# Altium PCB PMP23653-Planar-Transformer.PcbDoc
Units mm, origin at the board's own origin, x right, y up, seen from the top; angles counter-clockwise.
Board outline 30.4 x 20.9 mm, 6 copper layers (Top Layer, Int1, Int2, Int3, Int4, Bottom Layer), stack 2.081 mm thick; 6 components, 2 nets, 18 pads, 29 vias.
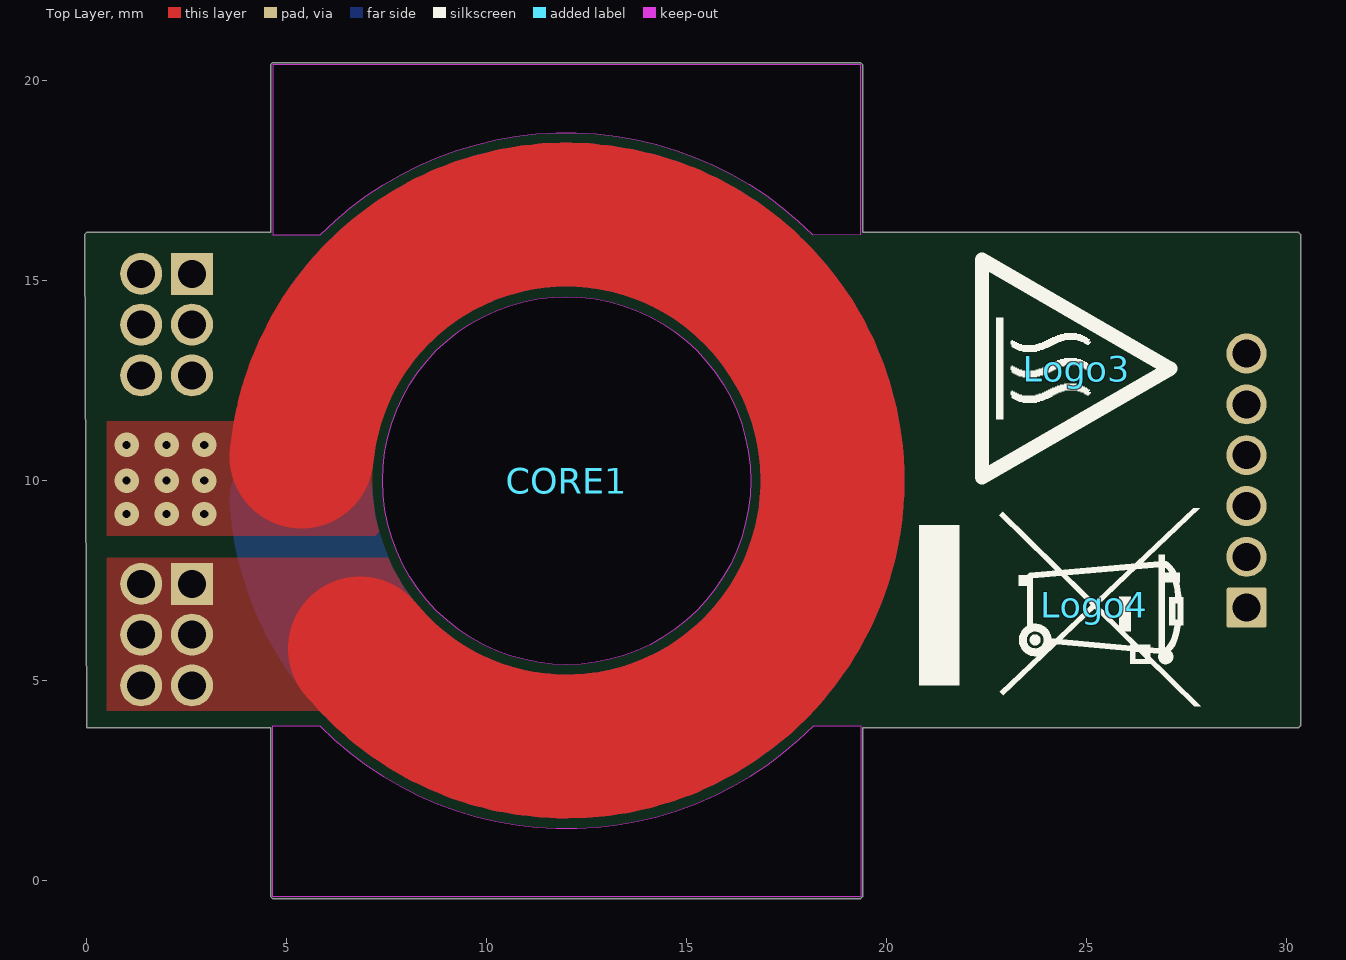
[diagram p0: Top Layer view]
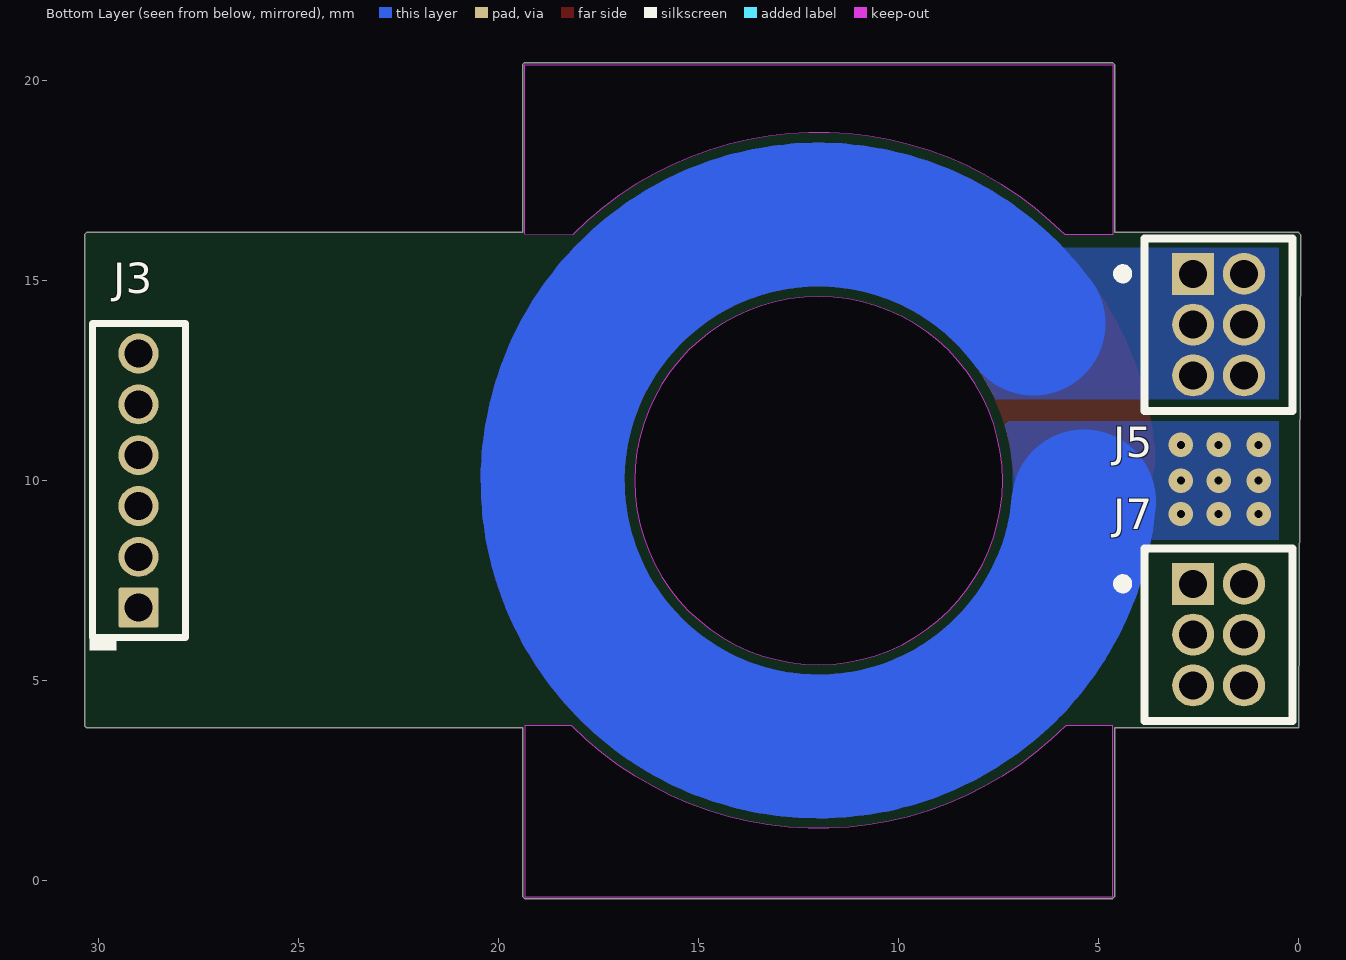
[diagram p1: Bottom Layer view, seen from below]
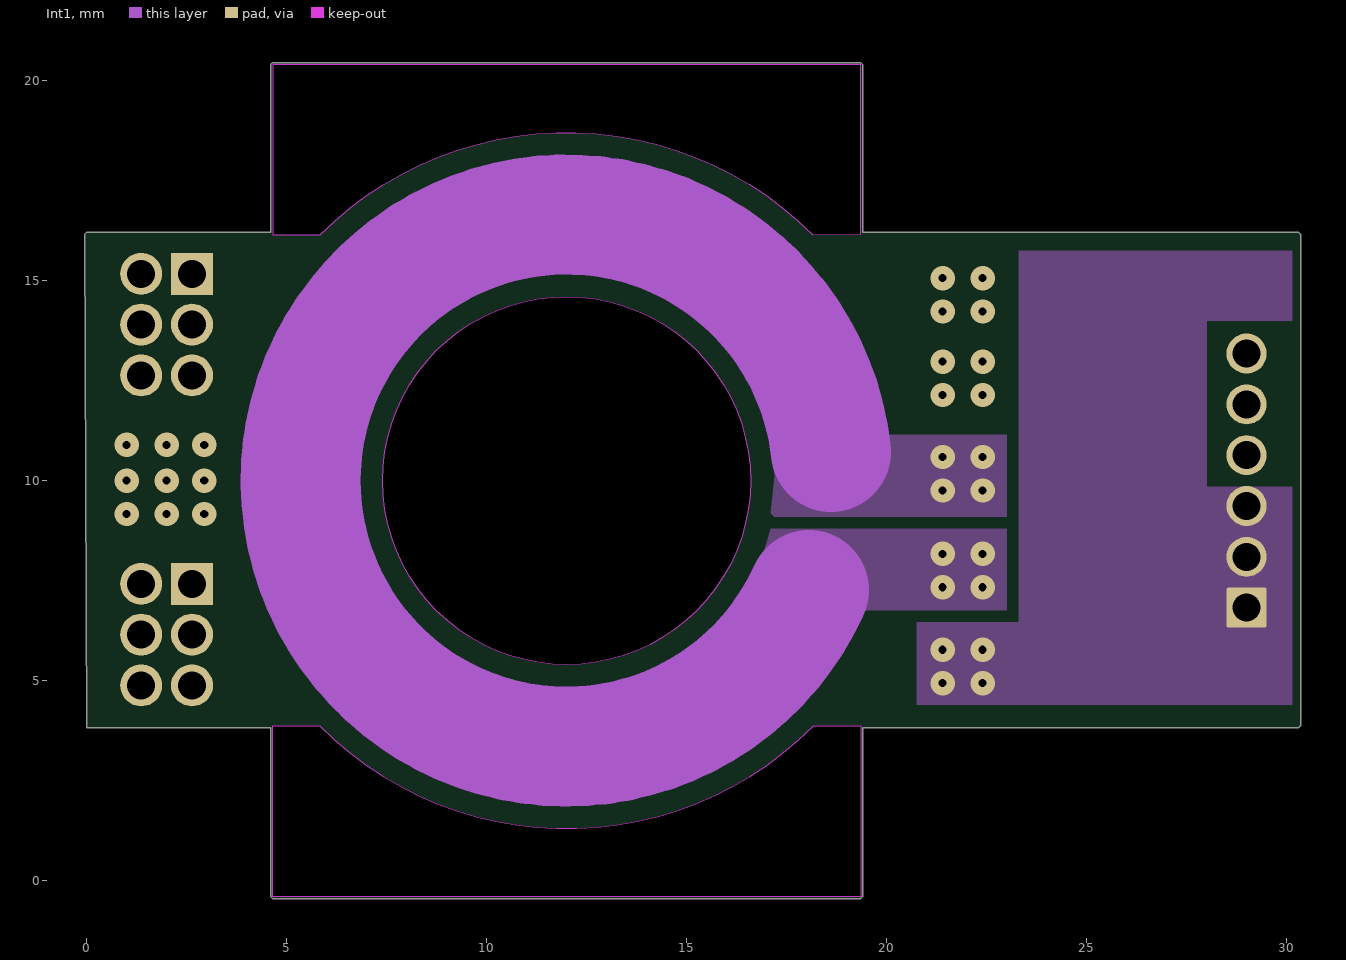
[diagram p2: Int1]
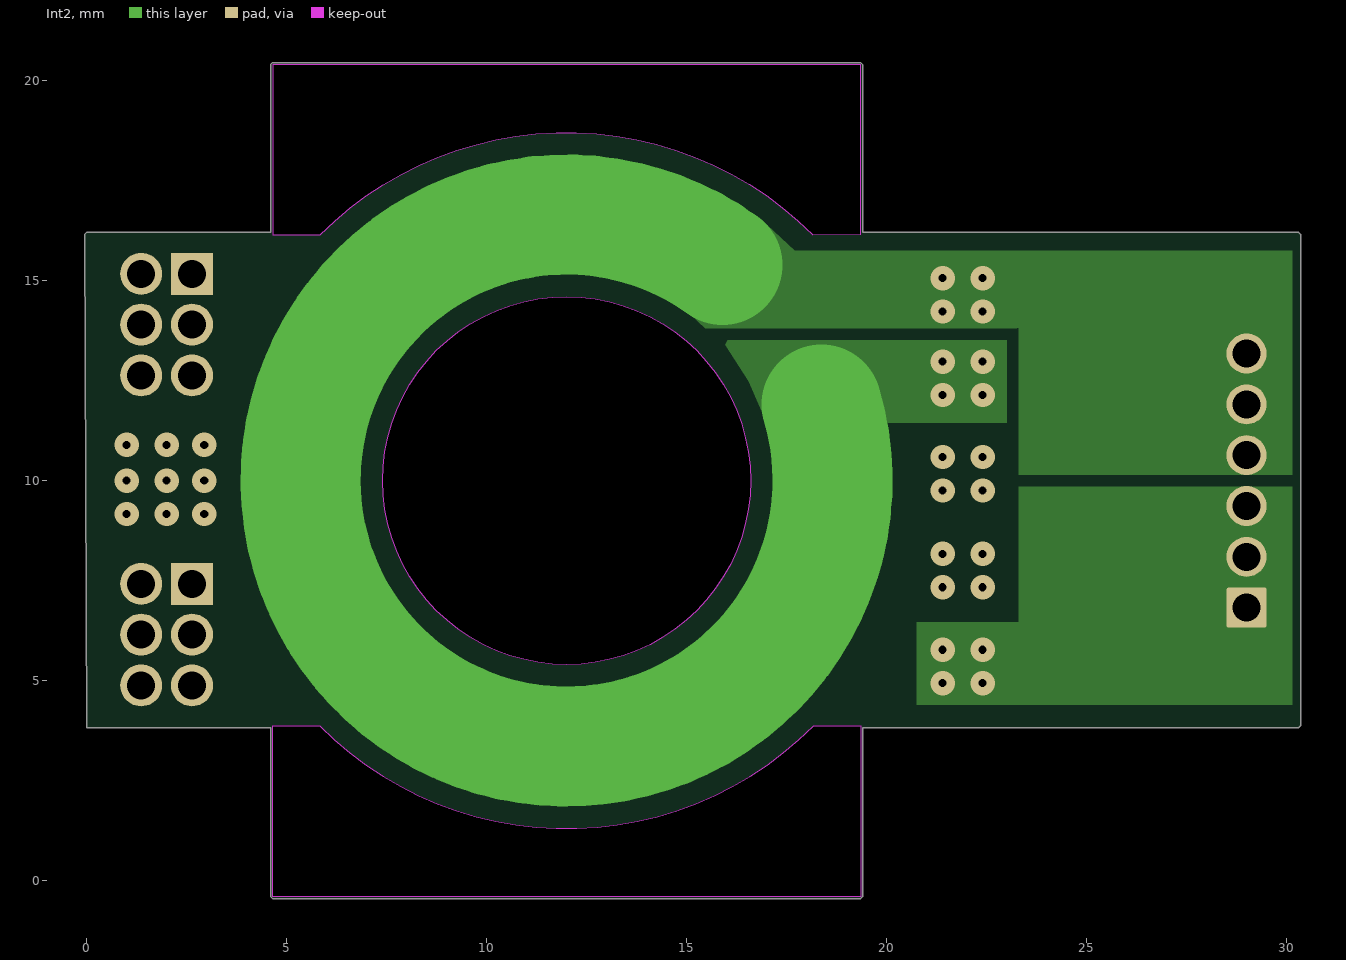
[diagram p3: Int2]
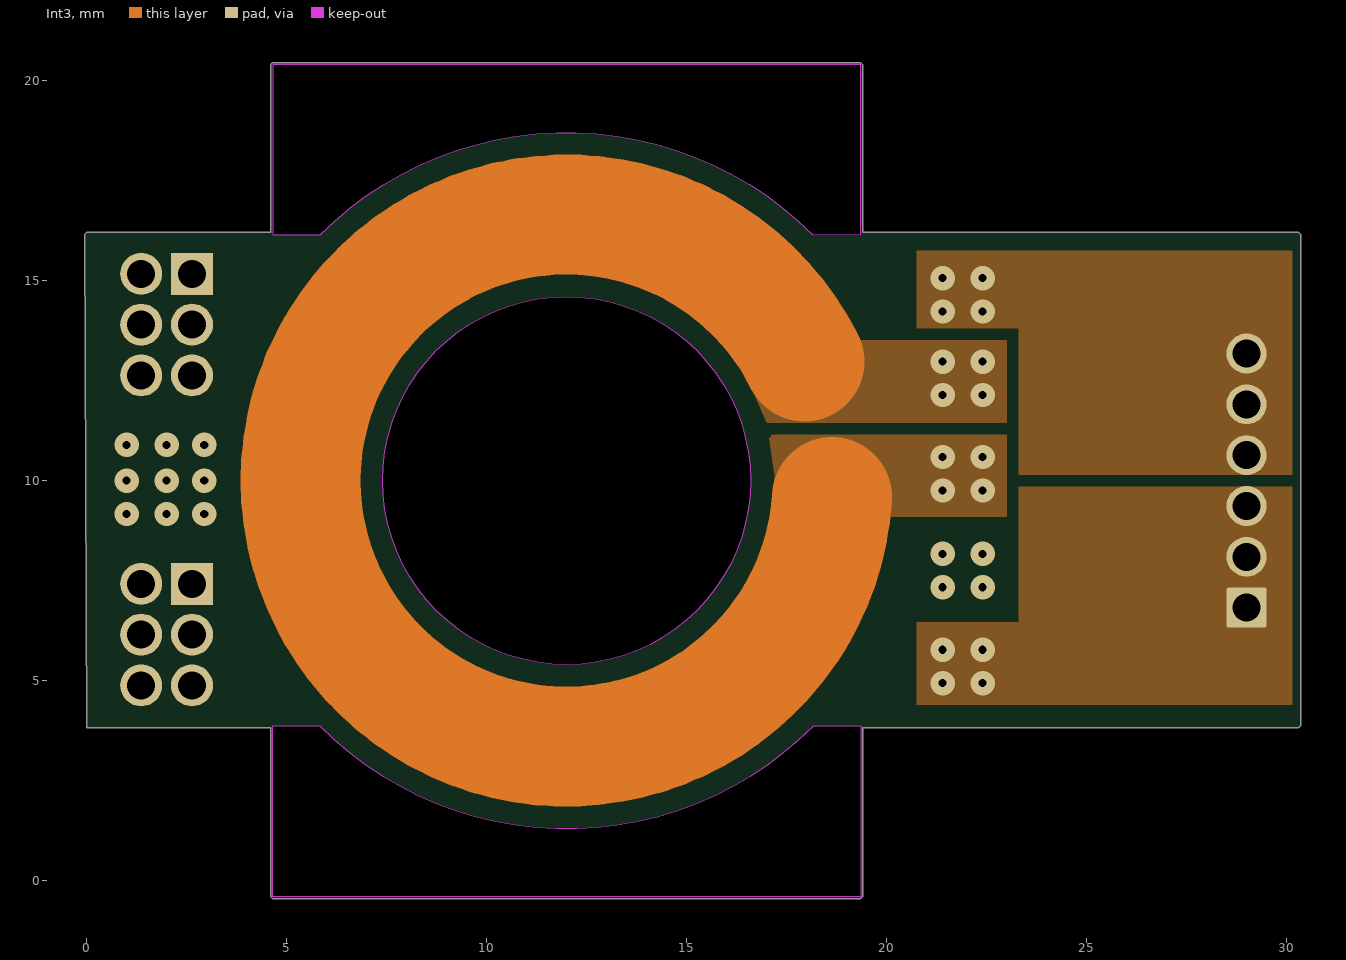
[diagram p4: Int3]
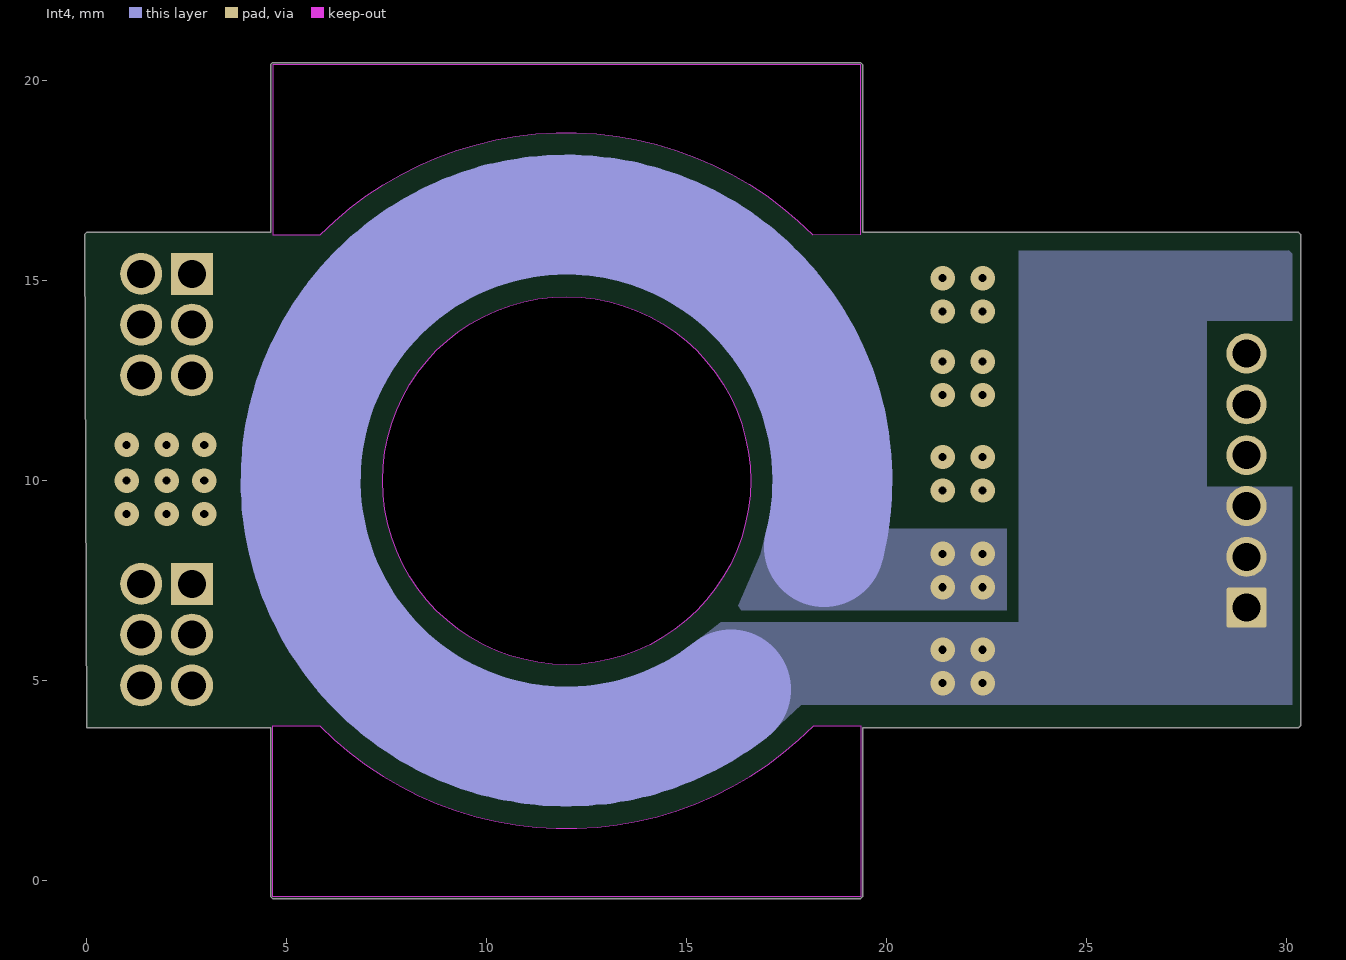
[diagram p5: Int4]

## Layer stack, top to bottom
Top Solder: solder mask 0.0254, SM-001, Dk 4
Top Layer: signal copper 0.07
Dielectric 1: core 0.508, Core-036, Dk 4.6
Dielectric 2: prepreg 0.0584, PP-003, Dk 3.9
Int1: signal copper 0.07
Dielectric 3: core 0.1778, Core-022, Dk 4.3
Int2: signal copper 0.07
Dielectric 4: prepreg 0.0864, PP-010, Dk 4
Dielectric 5: prepreg 0.0864, PP-010, Dk 4
Int3: signal copper 0.07
Dielectric 6: core 0.1778, Core-022, Dk 4.3
Int4: signal copper 0.07
Dielectric 7: prepreg 0.0584, PP-003, Dk 3.9
Dielectric 8: core 0.508, Core-036, Dk 4.6
Bottom Layer: signal copper 0.07
Bottom Solder: solder mask 0.0254, SM-001, Dk 4

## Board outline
0,3.823 4.6,3.823 4.6,-0.4 4.65,-0.45 19.35,-0.45 19.4,-0.4 19.4,3.823 30.3,3.823 30.35,3.873 30.35,16.152 30.3,16.202 19.4,16.202 19.4,20.4 19.35,20.45 4.65,20.45 4.6,20.4 4.601,16.202 0,16.202 -0.05,16.152

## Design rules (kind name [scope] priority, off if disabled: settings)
AcuteAngle [All] p1: minimum=4.50000000000000E+0001 checktracksonly=FALSE
AssemblyTestPointUsage [All] p1: valid=2
BoardOutlineClearance BoardOutlineClearance_MountingHoles [OnCopper and InComponentClass('Mounting Holes')] p1: gap=1 ignorepadtopadclearanceinfootprint=FALSE
BoardOutlineClearance BoardOutlineClearance_Poly [OnCopper and IsPoly] p2: gap=0.2 ignorepadtopadclearanceinfootprint=FALSE
BoardOutlineClearance BoardOutlineClearanceInner [OnCopper and IsPoly AND (OnLayer('Layer 1') OR OnLayer('Layer 2') OR OnLayer('Layer 3') OR OnLayer('Layer 4'))] p3: gap=0.5 ignorepadtopadclearanceinfootprint=FALSE
Clearance Clearance_Keepouts [((IsTrack Or IsArc) And Not InPoly) And IsFree and IsKeepOut vs ((IsTrack Or IsArc) And Not InPoly) And IsFree and IsKeepOut] p1: gap=0 ignorepadtopadclearanceinfootprint=FALSE
Clearance Clearance_Poly [InPolygon] p2: gap=0.254 ignorepadtopadclearanceinfootprint=TRUE
Clearance Clearance_FiducialMark [IsKeepOut and InComponentClass('FiducialMark') vs IsPad and InComponentClass('FiducialMark')] p3: gap=0 ignorepadtopadclearanceinfootprint=FALSE
Clearance [All] p4: gap=0.2 ignorepadtopadclearanceinfootprint=TRUE
ComponentClearance ComponentClearance_MountingHoles_FiducialMarks [InComponentClass('Mounting Holes') vs InComponentClass('FiducialMark')] p1: gap=1.27 collisioncheckmode=3 verticalgap=0.254 showdistances=FALSE
ComponentClearance ComponentClearance_Shunt [InComponentClass('Header') vs InComponentClass('Shunt')] p2: gap=0 collisioncheckmode=3 verticalgap=0 showdistances=FALSE
ComponentClearance ComponentClearance_Logo [InComponentClass('Logo')] p3: gap=0.762 collisioncheckmode=3 verticalgap=0.254 showdistances=FALSE
ComponentClearance ComponentClearance_ScrewToNut [(HasFootprint('NY PMS 440 0025 PH')) vs (HasFootprint('Keystone_1902C'))] p4: gap=0.127 collisioncheckmode=3 verticalgap=0.254 showdistances=FALSE
ComponentClearance ComponentClearance_MountingHoles [InComponentClass('Mounting Holes')] p5: gap=2.54 collisioncheckmode=3 verticalgap=2540 showdistances=FALSE
ComponentClearance ComponentClearance_SmallPassives [HasFootprint('0201*') or HasFootprint('0402*') or HasFootprint('0508') or HasFootprint('0603*') or HasFootprint('0612') or HasFootprint('0805*') or HasFootprint('0815*') or HasFootprint('0830*') or HasFootprint('1206*') or HasFootprint('1210*') or HasFootprint('1808*') or HasFootprint('1812*') or HasFootprint('1825*') or HasFootprint('2010*') or HasFootprint('2220*') or HasFootprint('2225*') or HasFootprint('2512*') or HasFootprint('2728*') or HasFootprint('3518*') vs HasFootprint('0201*') or HasFootprint('0402*') or HasFootprint('0508') or HasFootprint('0603*') or HasFootprint('0612') or HasFootprint('0805*') or HasFootprint('0815*') or HasFootprint('0830*') or HasFootprint('1206*') or HasFootprint('1210*') or HasFootprint('1808*') or HasFootprint('1812*') or HasFootprint('1825*') or HasFootprint('2010*') or HasFootprint('2220*') or HasFootprint('2225*') or HasFootprint('2512*') or HasFootprint('2728*') or HasFootprint('3518*')] p6: gap=0.38 collisioncheckmode=3 verticalgap=0.254 showdistances=FALSE
ComponentClearance ComponentClearance_THtoSMT [IsThruComponent vs IsSMTComponent] p7: gap=0.762 collisioncheckmode=3 verticalgap=0.762 showdistances=FALSE
ComponentClearance ComponentClearance_THtoTH [IsThruComponent vs IsThruComponent] p8: gap=0.508 collisioncheckmode=3 verticalgap=0.762 showdistances=FALSE
ComponentClearance [All] p9: gap=0.508 collisioncheckmode=3 verticalgap=0.254 showdistances=FALSE
DiffPairsRouting [All] p1: maxlimit=2.54 minlimit=0.254 mostfreqgap=0.254 toplayer_minwidth=0.381 toplayer_maxwidth=0.381 toplayer_prefwidth=0.381 midlayer1_minwidth=0.381 midlayer1_maxwidth=0.381 midlayer1_prefwidth=0.381 midlayer2_minwidth=0.381 midlayer2_maxwidth=0.381 midlayer2_prefwidth=0.381 midlayer3_minwidth=0.381 midlayer3_maxwidth=0.381 midlayer3_prefwidth=0.381 midlayer4_minwidth=0.381 midlayer4_maxwidth=0.381 midlayer4_prefwidth=0.381 bottomlayer_minwidth=0.381 bottomlayer_maxwidth=0.381 bottomlayer_prefwidth=0.381 maxuncoupledlength=25.4
FabricationTestPointUsage TestPointUsage [All] p1: valid=2 allowmultiple=FALSE
FabricationTestpoint Testpoint [All] p1: side=3 testpointundercomponent=TRUE minsize=1.016 maxsize=2.54 preferedsize=1.524 minholesize=0 maxholesize=1.016 preferedholesize=0.813 testpointgrid=0.025 allowsidetop=TRUE allowsidebottom=TRUE usegrid=TRUE gridtolerance=0
FanoutControl Fanout_LCC [IsLCC] p1: bgadir=Out bgaviamode=Centered fanoutstyle=Auto fanoutdirection=Alternating viagrid=0.025 // Fanout_LCC (Default Rule)
FanoutControl Fanout_BGA [IsBGA] p2: bgadir=Out bgaviamode=Centered fanoutstyle=Auto fanoutdirection=Alternating viagrid=0.025 // Fanout_BGA (Default Rule)
FanoutControl Fanout_Default [All] p4: bgadir=Out bgaviamode=Centered fanoutstyle=Auto fanoutdirection=Alternating viagrid=0.025 // Fanout_Default (Default Rule)
FanoutControl Fanout_Small [(CompPinCount < 5)] p5: bgadir=Out bgaviamode=Centered fanoutstyle=Auto fanoutdirection=OutThenIn viagrid=0.025 // Fanout_Small (Default Rule)
HoleSize [All] p1: absolutevalues=TRUE maxlimit=6.375 minlimit=0.2 maxpercent=80.000 minpercent=20.000
MinimumAnnularRing MinimumAnnularRing_ThermalPadVias [IsVia and InAnyComponent] p1: minimumring=0.15
MinimumAnnularRing [All] p2: minimumring=0.14
MinimumSolderMaskSliver MinimumSolderMaskSliver_Logo [InComponentClass('Logo') vs InComponentClass('Logo')] p1: minsoldermaskwidth=0.018
MinimumSolderMaskSliver [All] p2: minsoldermaskwidth=0.1
PlaneConnect [All] p1: planeconnectstyle=Direct reliefexpansion=0.254 reliefentries=4 reliefconductorwidth=0.254 reliefairgap=0.254
PolygonConnect [All] p1: connectstyle=Direct reliefconductorwidth=0.254 reliefentries=4 polygonreliefangle="90 Angle" airgapwidth=0.254
RoutingVias ThermalPadVias [IsVia and InAnyComponent] p1: holewidth=0.2 width=0.5 viastyle="Through Hole" minholewidth=0.2 minwidth=0.5 maxholewidth=0.33 maxwidth=0.6
RoutingVias [All] p2: holewidth=0.406 width=0.864 viastyle="Through Hole" minholewidth=0.2 minwidth=0.61 maxholewidth=1.016 maxwidth=1.651
SilkToBoardRegionClearance [Not ((IsComment or IsDesignator) And (Hide <> 'False')) and not InRegion(1000,500,4000,800)] p1:
SilkToSilkClearance SilkToSilkClearance_Pb-FreeLogo [(HasFootprint('Pb-Free_Overlay_Medium') OR HasFootprint('Pb-Free_Overlay_Small')) vs (HasFootprint('Pb-Free_Overlay_Medium') OR HasFootprint('Pb-Free_Overlay_Small'))] p1: silktosilkclearance=0
SilkToSilkClearance [All] p2: silktosilkclearance=0.1
SilkToSolderMaskClearance SilkToComponentPadClearance [(IsPad or IsFill or IsRegion) and InAnycomponent] p1: minsilkscreentomaskgap=0.127 clearancetoexposedcopper=TRUE
SilkToSolderMaskClearance "Silk to Solder Mask Opening" [All] p2: minsilkscreentomaskgap=0.1 clearancetoexposedcopper=FALSE
SolderMaskExpansion [All] p1: expansion=0.05 istentingtop=FALSE
UnRoutedNet [All] p1: checkbadconnections=TRUE
Width [All] p1: maxlimit=4 minlimit=0.152 preferedwidth=0.254 checkconnectedcopper=TRUE
14 further rules are at their usual default settings.

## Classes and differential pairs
net class Primary: NetJ5_1

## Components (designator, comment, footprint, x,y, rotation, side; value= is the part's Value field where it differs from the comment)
CORE1 "B66483G0000X149" PCBComponent_1 12,10 r0 top
J3 "SLV W 1 080 6 G" "SLV W 1 080 6 G" 29,10 r90 bottom
J5 "SLV W 4 080 6 G" "SLV W 4 080 6 G" 2,13.9 r180 bottom
J7 "SLV W 4 080 6 G" "SLV W 4 080 6 G" 2,6.15 r180 bottom
Logo3 "CAUTION HOT SURFACE" IEC_HotSurface_Small 24.75,12.8 r270 top
Logo4 "WEEE logo" WEEE_Minimum 25.197,6.882 r270 top

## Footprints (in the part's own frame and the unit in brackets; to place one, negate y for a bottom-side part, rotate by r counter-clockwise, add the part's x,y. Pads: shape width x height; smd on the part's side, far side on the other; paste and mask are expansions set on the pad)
IEC_HotSurface_Small [mm]
  silkscreen extent -2.72,-2.36 2.72,2.35
PCBComponent_1 [mm]
  Top Layer pour cut-out: 0,-4.6 -1.76,-4.25 -3.253,-3.253 -4.25,-1.76 -4.6,0 -4.6,0 -4.25,1.76 -3.253,3.253 -1.76,4.25 0,4.6 0,4.6 1.76,4.25 3.253,3.253 4.25,1.76 4.6,0 4.6,0 4.25,-1.76 3.253,-3.253 1.76,-4.25 0,-4.6
  Keep-Out Layer board cut-out: -7.348,6.152 -6.164,6.14 -3.341,8.033 -0.009,8.7 3.325,8.039 6.152,6.152 6.152,6.152 7.35,6.152 7.35,10.4 -7.35,10.4
  Keep-Out Layer board cut-out: -7.35,-10.4 -7.35,-6.127 -6.176,-6.127 -3.345,-8.031 0,-8.7 3.345,-8.031 6.176,-6.127 6.176,-6.127 7.35,-6.127 7.35,-10.4
  Keep-Out Layer board cut-out: 0,-4.6 -1.76,-4.25 -3.253,-3.253 -4.25,-1.76 -4.6,0 -4.6,0 -4.25,1.76 -3.253,3.253 -1.76,4.25 0,4.6 0,4.6 1.76,4.25 3.253,3.253 4.25,1.76 4.6,0 4.6,0 4.25,-1.76 3.253,-3.253 1.76,-4.25 0,-4.6
"SLV W 1 080 6 G" [mm] "SULLINS"
  rrect10% 1x1 hole 0.7: 1(-3.175,0)
  round 1 hole 0.7: 2(-1.905,0) 3(-0.635,0) 4(0.635,0) 5(1.905,0) 6(3.175,0)
  silkscreen extent -4.25,-1.17 3.93,1.22, body extent -3.85,-1.1 3.85,1.1, height 12.2
"SLV W 4 080 6 G" [mm] "Sullins"
  rect 1.05x1.05 hole 0.7 paste+0: 1(-0.635,1.27)
  round 1.05 hole 0.7 paste+0: 2(0.635,1.27) 3(-0.635,0) 4(0.635,0) 5(-0.635,-1.27) 6(0.635,-1.27)
  silkscreen extent -2.51,-2.15 1.85,2.15, body extent -1.85,-2.15 1.85,2.15, height 12.2
WEEE_Minimum [mm] "WEEElie bin"
  silkscreen extent -2.42,-4.38 2.52,2.65

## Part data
CORE1: library part "EQ Core", "EQ20 core set, N49 material, gapped to 1.1uH", Alternate Manufacturer=-, Manufacturer=TDK
J3 J5 J7: "Connector Header Through Hole 6 position 0.050\" (1.27mm)"
Logo3: library part CMP-0074837-2, "IEC 61010-1 Hot Surface Warning", Manufacturer="Texas Instruments"
Logo4: library part CMP-0074769-4, Manufacturer="Texas Instruments"

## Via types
v1: diameter 0.61, hole 0.203, Int1 to Int4, tented both sides, 20 vias
v2: diameter 0.61, hole 0.203, Top Layer to Bottom Layer, tented both sides, 9 vias

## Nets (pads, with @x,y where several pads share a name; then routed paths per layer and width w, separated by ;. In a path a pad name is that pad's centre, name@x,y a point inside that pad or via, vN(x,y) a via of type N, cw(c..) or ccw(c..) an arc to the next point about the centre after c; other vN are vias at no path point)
NetJ3_1: J3.1 J3.2 J3.3 J3.4 J3.5 J3.6 | length 151.4
  Int1 w3: 18.06,7.262 cw(c12,10) 18.611,10.717
  Int2 w3: 15.9,15.386 ccw(c12,10) 18.371,11.905
  Int3 w3: 17.948,12.973 ccw(c12,10) 18.637,9.59
  Int4 w3: 16.116,4.777 cw(c12,10) 18.441,8.345
  other v1: 21.401,4.937 22.401,4.937 21.401,5.772 22.401,5.772 21.401,7.332 22.401,7.332 21.401,8.167 22.401,8.167 21.401,9.753 22.401,9.753 21.401,10.588 22.401,10.588 21.401,12.138 22.401,12.138 21.401,12.973 22.401,12.973 21.401,14.227 22.401,14.227 21.401,15.062 22.401,15.062
NetJ5_1: J5.1 J5.2 J5.3 J5.4 J5.5 J5.6 J7.1 J7.2 J7.3 J7.4 J7.5 J7.6 | length 73.7
  Top Layer w3.6: 5.377,10.6 cw(c12,10) 6.84,5.806
  Bottom Layer w3.6: 5.37,9.483 ccw(c12,10) 6.629,13.921
  other v2: 1,9.165 2,9.165 2.942,9.165 1,10 2,10 2.942,10 1,10.891 2,10.891 2.942,10.891

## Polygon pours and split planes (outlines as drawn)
NetJ5_1 on Bottom Layer "BOTTOM_LAYER_NETJ5_1_P000" (solid, remove dead copper, pour order 0): 0.5,15.823 0.5,8.523 8.268,8.523 8.268,15.823
NetJ5_1 on Top Layer "TOP_LAYER_NETJ5_1_P001" (solid, remove dead copper, pour order 1): 0.5,11.482 0.5,4.25 8.268,4.25 8.268,11.482
NetJ3_1 on Int1 "INT1_NETJ3_1_P008" (solid, remove dead copper, pour order 8): 23.3,15.75 23.3,6.46 20.75,6.46 20.75,4.4 30.35,4.4 30.35,15.75
NetJ3_1 on Int1 "INT1_NETJ3_1_P003" (solid, remove dead copper, pour order 3): 17.1,8.79 16.8,7.775 16.01,6.76 23,6.76 23,8.79
NetJ3_1 on Int1 "INT1_NETJ3_1_P007" (solid, remove dead copper, pour order 7): 17.05,11.15 17.2,10.12 17.1,9.09 23,9.09 23,11.15
NetJ3_1 on Int3 "INT3_NETJ3_1_P012" (solid, remove dead copper, pour order 12): 23.3,10.147 23.3,13.81 20.75,13.81 20.75,15.75 30.35,15.75 30.35,10.147
NetJ3_1 on Int3 "INT3_NETJ3_1_P010" (solid, remove dead copper, pour order 10): 23.3,9.849 23.3,6.46 20.75,6.46 20.75,4.4 30.35,4.4 30.35,9.849
NetJ3_1 on Int3 "INT3_NETJ3_1_P009" (solid, remove dead copper, pour order 9): 17.05,11.15 17.2,10.12 17.1,9.09 23,9.09 23,11.15
NetJ3_1 on Int3 "INT3_NETJ3_1_P004" (solid, remove dead copper, pour order 4): 16.2,13.51 16.55,12.48 17,11.45 23,11.45 23,13.51
NetJ3_1 on Int2 "INT2_NETJ3_1_P014" (solid, remove dead copper, pour order 14): 23.3,9.849 23.3,6.46 20.75,6.46 20.75,4.4 30.35,4.4 30.35,9.849
NetJ3_1 on Int2 "INT2_NETJ3_1_P013" (solid, remove dead copper, pour order 13): 23.3,10.147 23.3,13.81 20.75,13.81 20.75,15.75 30.35,15.75 30.35,10.147
NetJ3_1 on Int2 "INT2_NETJ3_1_P005" (solid, remove dead copper, pour order 5): 15.1,16.4 15.1,14.14 15.47,13.81 23,13.81 23,15.75 17.7,15.75 17,16.4
NetJ3_1 on Int2 "INT2_NETJ3_1_P011" (solid, remove dead copper, pour order 11): 15.9,13.51 16.55,12.48 17,11.45 23,11.45 23,13.51
NetJ3_1 on Int4 "INT4_NETJ3_1_P006" (solid, remove dead copper, pour order 6): 17.01,8.79 16.849,8.167 16.25,6.76 23,6.76 23,8.79
NetJ3_1 on Int4 "INT4_NETJ3_1_P002" (solid, remove dead copper, pour order 2): 23.3,6.46 15.854,6.46 12.151,3.576 30.3,3.576 30.3,15.755 23.3,15.748

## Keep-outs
Keep-Out Layer:
  text ".Layer_Name" at 14.656,-21.806 h1.52

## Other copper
Top Layer:
  pour cut-out: 0,8.067 0,8.624 8.747,8.624 8.747,8.067
  text ".Layer_Name" at 14.656,-21.806 h1.52
Int1:
  pour cut-out: 28,14 28,9.849 30.3,9.849 30.3,14
  pour cut-out: 15.253,8.79 15.253,9.09 23,9.09 23,8.79
Int2:
  pour cut-out: 14.503,13.51 14.503,13.81 23.25,13.81 23.25,13.51
Int3:
  pour cut-out: 15.129,11.15 15.129,11.45 23,11.45 23,11.15
Int4:
  pour cut-out: 28,14 28,9.849 30.3,9.849 30.3,14
  pour cut-out: 16.122,2.777 17.867,4.4 30.3,4.4 30.3,2.777
  pour cut-out: 15,6.76 15,6.46 23,6.46 23,6.76
Bottom Layer:
  pour cut-out: 0,11.482 0,12.039 8.747,12.039 8.747,11.482
  text ".Layer_Name" at 14.656,-21.806 h1.52

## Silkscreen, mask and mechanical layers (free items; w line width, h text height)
Top Overlay:
  text ".Layer_Name" at 14.656,-21.806 h1.52
Bottom Overlay:
  text ".Layer_Name" at 14.656,-21.806 h1.52
Top Paste:
  text ".Layer_Name" at 14.656,-21.806 h1.52
Bottom Paste:
  text ".Layer_Name" at 14.656,-21.806 h1.52
Top Solder:
  text ".Layer_Name" at 14.656,-21.806 h1.52
  text ".Layer_Name" at 14.656,-21.806 h1.52
Bottom Solder:
  text ".Layer_Name" at 14.656,-21.806 h1.52
Drill Guide:
  text ".Layer_Name" at 14.656,-21.806 h1.52
M1 Board Outline:
  lines w0.1: 4.65,3.873 0,3.873 0,16.152 4.652,16.152 ; 19.35,3.873 30.3,3.873 30.3,16.152 19.35,16.152 ; -0.1,16.152 cw(c-0.05,16.152) -0.085,16.187 ; -0.1,16.152 cw(c-0.05,16.152) -0.086,16.187 -0.085,16.187 ; -0.1,16.152 -0.05,3.822 ; -0.085,16.187 -0.036,16.237 ; -0.05,3.822 ccw(c0,3.823) 0,3.773 ; -0.05,3.822 ccw(c0,3.823) 0,3.773 ; -0.035,16.238 cw(c0,16.202) 0,16.252 ; -0.036,16.237 cw(c0,16.202) 0,16.252 ; -0.036,16.237 -0.035,16.238 ; 0,3.773 4.55,3.773 4.55,-0.4 ; 0,16.252 4.551,16.252 4.55,20.4 ; 4.55,-0.4 ccw(c4.6,-0.4) 4.565,-0.436 ; 4.55,-0.4 ccw(c4.6,-0.4) 4.564,-0.435 ; 4.55,20.4 cw(c4.6,20.4) 4.564,20.435 ; 4.55,20.4 cw(c4.6,20.4) 4.564,20.435 ; 4.564,-0.435 4.565,-0.436 ; 4.565,-0.436 4.614,-0.485 ; 4.564,20.435 4.615,20.486 ; 4.6,3.873 cw(c4.65,3.873) 4.6,3.873 ; 4.6,3.873 ccw(c4.6,3.823) 4.6,3.873 ; 4.6,3.873 ccw(c4.6,3.823) 4.6,3.873 ; 4.6,3.873 4.6,3.873 ; 4.6,3.873 0.05,3.873 0,16.131 0.021,16.152 4.601,16.152 ; 4.6,3.873 cw(c4.65,3.873) 4.65,3.923 ; 4.6,3.873 cw(c4.65,3.873) 4.65,3.923 ; 4.602,16.152 ccw(c4.652,16.152) 4.651,16.102 ; 4.602,16.152 ccw(c4.652,16.152) 4.602,16.152 ; 4.602,16.152 ccw(c4.652,16.152) 4.651,16.102 ; 4.602,16.152 ccw(c4.601,16.202) 4.602,16.152 ; 4.601,16.152 ccw(c4.601,16.202) 4.602,16.152 ; 4.602,16.152 ccw(c4.601,16.202) 4.602,16.152 ; 4.601,16.152 ccw(c4.601,16.202) 4.602,16.152 ; 4.602,16.152 4.602,16.152 ; 4.614,-0.485 ccw(c4.65,-0.45) 4.65,-0.5 ; 4.614,-0.485 4.615,-0.486 ccw(c4.65,-0.45) 4.65,-0.5 ; 4.615,20.486 cw(c4.65,20.45) 4.65,20.5 ; 4.615,20.486 cw(c4.65,20.45) 4.65,20.5 ; 4.65,-0.5 19.35,-0.5 ; 4.65,3.923 5.824,3.923 ; 4.65,20.5 19.35,20.5 ; 4.651,16.102 5.835,16.09 ; 5.824,3.923 cw(c5.824,3.873) 5.859,3.908 ; 5.824,3.923 cw(c5.824,3.873) 5.859,3.908 ; 5.835,16.09 ccw(c5.836,16.14) 5.871,16.104 ; 5.835,16.09 ccw(c5.836,16.14) 5.871,16.104 ; 5.859,3.908 ccw(c12,10) 18.141,3.908 ; 5.871,16.104 cw(c12,10) 18.116,16.117 ; 18.116,16.117 ccw(c18.152,16.152) 18.152,16.102 ; 18.116,16.116 ccw(c18.152,16.152) 18.152,16.102 ; 18.116,16.116 ccw(c12,10) 18.116,16.117 ; 18.141,3.908 cw(c18.176,3.873) 18.176,3.923 ; 18.141,3.908 cw(c18.176,3.873) 18.176,3.923 ; 18.152,16.102 19.35,16.102 ; 18.176,3.923 19.35,3.923 ; 19.35,-0.5 ccw(c19.35,-0.45) 19.386,-0.485 ; 19.35,-0.5 ccw(c19.35,-0.45) 19.385,-0.486 ; 19.35,3.923 cw(c19.35,3.873) 19.4,3.873 ; 19.35,3.923 cw(c19.35,3.873) 19.4,3.873 ; 19.35,16.102 ccw(c19.35,16.152) 19.4,16.152 ; 19.35,16.102 ccw(c19.35,16.152) 19.4,16.152 ; 19.35,20.5 cw(c19.35,20.45) 19.386,20.485 ; 19.35,20.5 cw(c19.35,20.45) 19.385,20.486 19.386,20.485 ; 19.386,-0.485 19.435,-0.436 ; 19.385,-0.486 19.386,-0.485 ; 19.386,20.485 19.435,20.436 ; 19.4,3.873 ccw(c19.4,3.823) 19.4,3.873 ; 19.4,3.873 ccw(c19.35,3.873) 19.4,3.873 ; 19.4,3.873 ccw(c19.4,3.823) 19.4,3.873 ; 19.4,3.873 30.279,3.873 30.3,3.894 30.3,16.131 30.279,16.152 19.4,16.152 ; 19.4,3.873 19.4,3.873 ; 19.4,16.152 ccw(c19.4,16.202) 19.4,16.152 ; 19.4,16.152 ccw(c19.4,16.202) 19.4,16.152 ; 19.4,16.152 ccw(c19.35,16.152) 19.4,16.152 ; 19.4,16.152 19.4,16.152 ; 19.436,-0.435 ccw(c19.4,-0.4) 19.45,-0.4 ; 19.435,-0.436 ccw(c19.4,-0.4) 19.45,-0.4 ; 19.435,-0.436 19.436,-0.435 ; 19.436,20.435 cw(c19.4,20.4) 19.45,20.4 ; 19.435,20.436 cw(c19.4,20.4) 19.45,20.4 ; 19.435,20.436 19.436,20.435 ; 19.45,-0.4 19.45,3.773 30.3,3.773 ; 19.45,20.4 19.45,16.252 30.3,16.252 ; 30.3,3.773 ccw(c30.3,3.823) 30.336,3.788 ; 30.3,3.773 ccw(c30.3,3.823) 30.335,3.787 ; 30.3,16.252 cw(c30.3,16.202) 30.335,16.238 30.336,16.237 ; 30.3,16.252 cw(c30.3,16.202) 30.336,16.237 ; 30.336,3.788 30.385,3.837 ; 30.335,3.787 30.336,3.788 ; 30.336,16.237 30.385,16.188 ; 30.385,3.837 ccw(c30.35,3.873) 30.4,3.873 ; 30.386,3.838 ccw(c30.35,3.873) 30.4,3.873 ; 30.385,3.837 30.386,3.838 ; 30.386,16.187 cw(c30.35,16.152) 30.4,16.152 ; 30.385,16.188 cw(c30.35,16.152) 30.4,16.152 ; 30.385,16.188 30.386,16.187 ; 30.4,3.873 30.4,16.152 ; 4.7,-0.35 4.7,3.823 5.803,3.823 ccw(c12,10) 18.197,3.823 19.3,3.823 19.3,-0.35 4.7,-0.35 ; 4.7,20.35 4.702,16.201 5.815,16.19 cw(c12,10) 18.173,16.202 19.3,16.202 19.3,20.35 4.7,20.35 ; 7.35,10 cw(c12,10) 12,14.65 cw(c12,10) 16.65,10 cw(c12,10) 12,5.35 cw(c12,10) 7.35,10 ; 7.45,10 cw(c12,10) 12,14.55 cw(c12,10) 16.55,10 cw(c12,10) 12,5.45 cw(c12,10) 7.45,10
  text ".Layer_Name" at 14.656,-21.806 h1.52
M2 Board Dimensions:
  rectangle: 0,-6.985 3.175,-3.81
  rectangle: 3.175,-10.16 12.7,-6.985
  lines w0.178: 0,-6.985 25.4,-6.985 ; 3.175,-10.16 3.175,-3.81 ; 6.35,-10.16 6.35,-3.81 ; 12.7,-10.16 12.7,-3.81 ; 19.05,-10.16 19.05,-3.81 ; 0,-10.16 25.4,-10.16 25.4,-3.81 0,-3.81 0,-10.16
  text ".Layer_Name" at 14.656,-21.806 h1.52
M3 3D STEP Top:
  text ".Layer_Name" at 14.656,-21.806 h1.52
M4 3D STEP Bottom:
  text ".Layer_Name" at 14.656,-21.806 h1.52
M5 Assembly Top:
  lines w0.254: -7.417,-23.626 160.223,-23.626 ; -7.417,-18.462 160.274,-18.462 ; -7.417,-13.297 -7.417,-28.791 94.31,-28.791 160.274,-28.791 160.274,-13.297 -7.404,-13.297 -7.404,-28.791 32.614,-28.791 ; 55.194,-28.791 55.194,-13.297 ; 87.376,-18.462 87.376,-13.297 ; 108.712,-18.462 108.712,-13.297 ; 124.511,-28.956 124.511,-23.804
  text "COMPONENTS MARKED 'DNP' SHOULD NOT BE POPULATED." at 29.299,-8.09 h1.52
  text "ASSEMBLY VARIANT:" at 29.286,-11.024 h1.52
  text ".VariantName" at 55.601,-11.024 h1.52
  text "PCB VIEWED FROM TOP SIDE" at -5.804,-16.654 h1.52
  text "BOARD #:" at 57.099,-16.654 h1.52
  text ".PRJ_Number" at 70.955,-16.654 h1.52
  text "REV:" at 92.405,-16.654 h1.52
  text ".PCB_Rev" at 99.809,-16.654 h1.52
  text "SVN REV:" at 113.69,-16.654 h1.52
  text ".VersionControl_RevNumber" at 126.543,-16.654 h1.52
  text "TID #:" at 57.099,-21.819 h1.52
  text ".TID" at 70.955,-21.819 h1.52
  text "PLOT NAME =" at -5.804,-27.034 h1.52
  text ".plot_File_Name" at 14.656,-27.034 h1.52
  text "GENERATED    :" at 57.15,-27.034 h1.52
  text ".Print_Date" at 79.235,-27.034 h1.52
  text ".Print_Time" at 97.752,-27.034 h1.52
  text "TEXAS INSTRUMENTS" at 129.87,-27.034 h1.52
M6 Assembly Bottom:
  lines w0.254: -7.429,-18.474 160.261,-18.474 ; -7.379,-23.639 160.261,-23.639 ; 28.334,-28.969 28.334,-23.817 ; 44.133,-18.474 44.133,-13.31 ; 65.468,-18.474 65.468,-13.31 ; 97.65,-28.804 97.65,-13.31 ; 120.231,-28.804 160.249,-28.804 160.249,-13.31 -7.429,-13.31 -7.429,-28.804 58.534,-28.804 160.261,-28.804 160.261,-13.31
  text "COMPONENTS MARKED 'DNP' SHOULD NOT BE POPULATED." at 154.991,-8.077 h1.52
  text ".VariantName" at 128.473,-11.024 h1.52
  text "ASSEMBLY VARIANT:" at 154.864,-11.024 h1.52
  text ".VersionControl_RevNumber" at 26.302,-16.667 h1.52
  text "SVN REV:" at 39.154,-16.667 h1.52
  text ".PCB_Rev" at 53.035,-16.667 h1.52
  text "REV:" at 60.439,-16.667 h1.52
  text ".PRJ_Number" at 81.89,-16.667 h1.52
  text "BOARD #:" at 95.745,-16.667 h1.52
  text "PCB VIEWED FROM BOTTOM SIDE" at 158.648,-16.667 h1.52
  text ".TID" at 81.89,-21.831 h1.52
  text "TID #:" at 95.745,-21.831 h1.52
  text "TEXAS INSTRUMENTS" at 22.974,-27.047 h1.52
  text ".Print_Time" at 55.093,-27.047 h1.52
  text ".Print_Date" at 73.609,-27.047 h1.52
  text "GENERATED    :" at 95.694,-27.047 h1.52
  text ".plot_File_Name" at 138.189,-27.047 h1.52
  text "PLOT NAME =" at 158.648,-27.047 h1.52
M9 Title Sheet:
  drawing of 57 lines, arcs and shapes, not listed
  text "1" at 18.792,204.127 h1.78
  text "2" at 82.182,204.127 h1.78
  text "3" at 145.411,204.127 h1.78
  text "4" at 209.08,204.127 h1.78
  text "5" at 272.555,204.127 h1.78
  text "6" at 336.182,204.127 h1.78
  text "A" at -10.579,175.095 h1.78
  text "A" at 365.341,175.095 h1.78
  text "B" at -10.579,114.643 h1.78
  text "B" at 365.341,114.643 h1.78
  text "C" at -10.579,54.318 h1.78
  text "C" at 365.341,54.318 h1.78
  text "PROJECT TITLE:" at 288.125,7.048 h1.14
  text ".PRJ_Title" at 289.395,3.662 h1.78
  text "DESIGNED FOR:" at 288.125,-0.597 h1.14
  text ".PRJ_Customer" at 289.395,-4.153 h1.78
  text "D" at -10.579,-5.88 h1.78
  text "D" at 365.341,-5.88 h1.78
  text "FILE NAME:" at 288.125,-8.217 h1.14
  text ".PCB_File_Name_No_Path" at 289.395,-11.265 h1.78
  text "Texas Instruments (TI) and/or its licensors do not warrant the accuracy or completeness of this specification" at 161.9,-15.376 h1.14
  text "ENGINEER:" at 288.125,-15.583 h1.14
  text "LAYOUT BY:" at 326.352,-15.583 h1.14
  text "or any information contained therein. TI and/or its licensors do not warrant that this design will meet" at 160.757,-18.237 h1.14
  text ".PRJ_Engineer" at 289.395,-19.52 h1.78
  text ".PCB_Layout" at 327.635,-19.52 h1.78
  text "the specifications, will be suitable for your application or fit for any particular purpose, or will operate in" at 160.757,-21.099 h1.14
  text ".Layer_Name" at 14.656,-21.806 h1.52
  text "ALTIUM DESIGNER VERSION:" at 326.352,-23.457 h1.14
  text "an implementation. TI and/or its licensors do not warrant that the design is production worthy. You should" at 160.757,-23.961 h1.14
  text "completely validate and test your design implementation to confirm the system functionality for your application." at 161.9,-26.822 h1.14
  text ".print_Scale" at 289.395,-26.843 h1.78
  text ".Application_BuildNumber" at 327.635,-26.843 h1.78
  text "1" at 18.792,-32.093 h1.78
  text "2" at 82.182,-32.093 h1.78
  text "3" at 145.411,-32.093 h1.78
  text "4" at 209.08,-32.093 h1.78
  text "5" at 272.555,-32.093 h1.78
  text "6" at 336.182,-32.093 h1.78
M10 Fab Notes:
  drawing of 189 lines, arcs and shapes, not listed
  text "DESIGN INFORMATION" at 314.503,161.447 h1.52
  text "MIN. TRACK WIDTH:" at 298.131,158.091 h1.52
  text "8" at 325.976,158.091 h1.52
  text "MIL" at 329.907,158.091 h1.52
  text "7.874" at 321.75,155 h1.52
  text "MIN. CLEARANCE:" at 298.131,154.938 h1.52
  text "MIL" at 329.907,154.938 h1.52
  text "MIN. VIA PAD SIZE:" at 298.131,151.785 h1.52
  text "24" at 325.214,151.785 h1.52
  text "MIL" at 329.907,151.785 h1.52
  text "0.05mm (2MIL)" at 315.784,148.486 h1.52
  text "MINIMUM ANNULAR RING" at 289.769,148.277 h1.52
  text "EXTERNAL" at 333.768,148.277 h1.52
  text "PER" at 294.849,145.48 h1.52
  text "IPC-D-275 CLASS 2 LEVEL C" at 300.437,145.48 h1.52
  text "MIL, HOLES" at 338.238,142.928 h1.52
  text "+/-" at 328.27,142.709 h1.52
  text "+/-" at 349.961,142.709 h1.52
  text "REGISTRATION TOLERANCES:" at 289.769,142.682 h1.52
  text "METAL" at 320.243,142.682 h1.52
  text "5" at 334.879,142.683 h1.52
  text "3" at 356.037,142.683 h1.52
  text "MIL" at 358.99,142.682 h1.52
  text "HOLE SIZE TOLERANCE (UNLESS OTHERWISE SPECIFIED):" at 289.769,140.185 h1.52
  text "+/-" at 349.961,140.112 h1.52
  text "3" at 356.037,140.085 h1.52
  text "MIL" at 358.99,140.085 h1.52
  text "MATERIAL:" at 287.87,136.589 h1.52
  text "FR-4 High Tg" at 312.926,133.324 h1.52
  text "X" at 309.257,133.122 h1.52
  text "FR-4" at 298.563,133.007 h1.52
  text "OTHER" at 336.358,133.007 h1.52
  text "62 MIL (1.6mm) +/-10%" at 306.694,129.374 h1.52
  text "X" at 303.643,129.312 h1.52
  text "THICKNESS:" at 289.769,129.165 h1.52
  text "OTHER" at 339.33,129.165 h1.52
  text "TOLERANCE:" at 289.769,125.652 h1.52
  text "X" at 311.314,125.652 h1.52
  text "ANSI IPC-6012 TYPE 3 CLASS 2" at 315.836,125.652 h1.52
  text "OTHER +/-" at 315.835,121.989 h1.52
  text "BOW & TWIST:" at 289.769,118.302 h1.52
  text "X" at 311.314,118.302 h1.52
  text "ANSI IPC-6012 TYPE 3 CLASS 2" at 315.836,118.302 h1.52
  text "OTHER +/-" at 315.835,114.576 h1.52
  text "DRILLING:" at 287.87,111.258 h1.52
  text "NC_DRILL FILES" at 332.599,108.586 h1.52
  text "REFERENCE:" at 289.769,108.486 h1.52
  text "X" at 306.463,108.484 h1.52
  text "AS SHOWN" at 310.984,108.486 h1.52
  text "X" at 329.348,108.486 h1.52
  text "OTHER" at 340.168,104.873 h1.52
  text "PTH COPPER THICKNESS:" at 289.761,104.783 h1.52
  text "X" at 318.697,104.783 h1.52
  text "20-30 um" at 321.948,104.783 h1.52
  text "BOARD FINISH:" at 287.87,101.034 h1.52
  text "SILKSCREEN:" at 291.812,98.237 h1.52
  text "X" at 316.14,98.237 h1.52
  text "TOP" at 319.112,98.237 h1.52
  text "X" at 329.094,98.237 h1.52
  text "BOTTOM" at 332.091,98.237 h1.52
  text "SILKSCREEN COLOR:" at 291.812,94.295 h1.52
  text "X" at 316.115,94.295 h1.52
  text "WHITE" at 319.112,94.295 h1.52
  text "OTHER" at 332.091,94.295 h1.52
  text "X" at 319.442,90.652 h1.52
  text "GREEN" at 322.439,90.652 h1.52
  text "OTHER" at 338.136,90.652 h1.52
  text "SOLDER RESIST COLOR:" at 291.812,90.477 h1.52
  text "X" at 319.442,86.734 h1.52
  text "MATTE" at 322.439,86.734 h1.52
  text "SEMI-GLOSS" at 338.125,86.717 h1.52
  text "IMMERSION GOLD (ENIG)" at 314.819,82.345 h1.52
  text "ENEPIG" at 348.793,82.162 h1.52
  text "SURFACE FINISH:" at 287.87,82.136 h1.52
  text "X" at 310.298,82.136 h1.52
  text "IMM. TIN/SILVER OR EQUIV" at 296.24,78.649 h1.52
  text "OTHER" at 332.599,78.549 h1.52
  text "ARRAY/PANEL:" at 287.87,74.602 h1.52
  text "CUT AND TRIM PER M1 BOARD OUTLINE" at 314.819,74.393 h1.52
  text "N.C. ROUTE" at 314.819,70.94 h1.52
  text "X" at 332.295,70.94 h1.52
  text "V. SCORE" at 336.816,70.94 h1.52
  text "CERTIFICATION:" at 287.87,67.66 h1.52
  text "MATERIALS AND WORKMANSHIP FOR ALL PCBS" at 306.285,67.66 h1.52
  text "TO MEET OR EXCEED THE REQUIREMENTS OF:" at 306.285,65.271 h1.52
  text "X" at 297.078,62.003 h1.52
  text "ANSI IPC-A-600F CLASS ->" at 300.329,62.003 h1.52
  text "X" at 342.188,62.003 h1.52
  text "2" at 344.982,62.003 h1.52
  text "1" at 336.981,61.965 h1.52
  text "3" at 353.973,61.965 h1.52
  text "X" at 317.702,58.252 h1.52
  text "RoHS" at 320.953,58.252 h1.52
  text "OTHER" at 337.321,58.252 h1.52
  text "PER ORDER" at 347.407,58.252 h1.52
  text "ALL BOARDS MUST MEET OR EXCEED UL94-V0 REQUIREMENTS." at 288.569,54.345 h1.52
  text "PCB MUST BEAR THE UL94V-0 UL REGISTERED MATERIAL ID NUMBER" at 288.569,51.397 h1.52
  text "ADDITIONAL REQUIREMENTS:" at 287.87,47.094 h1.52
  text "MICROSECTION:" at 289.769,44.373 h1.52
  text "YES" at 312.775,44.373 h1.52
  text "REQUIRED" at 334.657,40.707 h1.52
  text "BARE BOARD ELEC. TEST:" at 289.769,40.634 h1.52
  text "NONE" at 322.935,40.634 h1.52
  text "X" at 331.66,40.634 h1.52
  text "PER ORDER" at 349.693,40.634 h1.52
  text "XX MIL VIAS REQUIRE NON-CONDUCTIVE FILL AND PLANARIZE" at 294.04,35.428 h1.5
  text "XX MIL VIAS REQUIRE CONDUCTIVE FILL AND PLANARIZE" at 294.243,32.787 h1.52
  text "OUTER XX MIL TRACES REQUIRE 50 OHM SINGLE-ENDED IMPEDANCE" at 294.218,28.637 h1.47
  text "LAYER 2 & 3 (INNER LAYERS) XX MIL WIDE, XX MIL SPACE / TRACES REQUIRE 100 OHM DIFFERENTIAL IMPEDANCE" at 294.015,22.65 h1.52
  text ".Layer_Name" at 14.656,-21.806 h1.52
M11 Gerber Information:
  lines w0.254: -7.417,-23.626 160.223,-23.626 ; -7.417,-18.462 160.274,-18.462 ; -7.417,-13.297 -7.417,-28.791 94.31,-28.791 160.274,-28.791 160.274,-13.297 -7.404,-13.297 -7.404,-28.791 32.614,-28.791 ; 55.194,-28.791 55.194,-13.297 ; 87.376,-18.462 87.376,-13.297 ; 108.712,-18.462 108.712,-13.297 ; 124.511,-28.956 124.511,-23.804
  text "ALL ARTWORK VIEWED FROM TOP SIDE" at -5.804,-16.654 h1.52
  text "BOARD #:" at 57.099,-16.654 h1.52
  text ".PRJ_Number" at 70.955,-16.654 h1.52
  text "REV:" at 92.405,-16.654 h1.52
  text ".PCB_Rev" at 99.809,-16.654 h1.52
  text "SVN REV:" at 113.69,-16.654 h1.52
  text ".VersionControl_RevNumber" at 126.543,-16.654 h1.52
  text "LAYER NAME =" at -5.804,-21.806 h1.52
  text "TID #:" at 57.099,-21.819 h1.52
  text ".TID" at 70.955,-21.819 h1.52
  text "PLOT NAME =" at -5.804,-27.034 h1.52
  text ".plot_File_Name" at 14.656,-27.034 h1.52
  text "GENERATED    :" at 57.15,-27.034 h1.52
  text ".Print_Date" at 79.235,-27.034 h1.52
  text ".Print_Time" at 97.752,-27.034 h1.52
  text "TEXAS INSTRUMENTS" at 129.87,-27.034 h1.52
M12 Stackup:
  drawing of 529 lines, arcs and shapes, not listed
  text "Layer" at 249.469,200.023 h1.52
  text "Name" at 259.88,200.023 h1.52
  text "Material" at 293.653,200.023 h1.52
  text "Thickness" at 308.889,200.023 h1.52
  text "Constant" at 325.395,200.023 h1.52
  text "Board Layer Stack" at 339.869,200.023 h1.52
  text "Top Overlay" at 259.88,196.975 h1.52
  text "Top Solder" at 259.88,193.927 h1.52
  text "SM-001" at 293.653,193.927 h1.52
  text "1.00mil" at 308.889,193.927 h1.52
  text "4" at 325.395,193.927 h1.52
  text "Top Surface Finish" at 259.88,190.879 h1.52
  text "PbSn" at 293.653,190.879 h1.52
  text "0.79mil" at 308.889,190.879 h1.52
  text "1" at 249.469,187.831 h1.52
  text "Top Layer" at 259.88,187.831 h1.52
  text "CF-005" at 293.653,187.831 h1.52
  text "2.76mil" at 308.889,187.831 h1.52
  text "Dielectric 1" at 259.88,184.783 h1.52
  text "Core-036" at 293.653,184.783 h1.52
  text "20.00mil" at 308.889,184.783 h1.52
  text "4.6" at 325.395,184.783 h1.52
  text "Dielectric 2" at 259.88,181.735 h1.52
  text "PP-003" at 293.653,181.735 h1.52
  text "2.30mil" at 308.889,181.735 h1.52
  text "3.9" at 325.395,181.735 h1.52
  text "2" at 249.469,178.687 h1.52
  text "Int1" at 259.88,178.687 h1.52
  text "CF-005" at 293.653,178.687 h1.52
  text "2.76mil" at 308.889,178.687 h1.52
  text "Dielectric 3" at 259.88,175.639 h1.52
  text "Core-022" at 293.653,175.639 h1.52
  text "7.00mil" at 308.889,175.639 h1.52
  text "4.3" at 325.395,175.639 h1.52
  text "3" at 249.469,172.591 h1.52
  text "Int2" at 259.88,172.591 h1.52
  text "CF-005" at 293.653,172.591 h1.52
  text "2.76mil" at 308.889,172.591 h1.52
  text "Dielectric 4" at 259.88,169.543 h1.52
  text "PP-010" at 293.653,169.543 h1.52
  text "3.40mil" at 308.889,169.543 h1.52
  text "4" at 325.395,169.543 h1.52
  text "Dielectric 5" at 259.88,166.495 h1.52
  text "PP-010" at 293.653,166.495 h1.52
  text "3.40mil" at 308.889,166.495 h1.52
  text "4" at 325.395,166.495 h1.52
  text "4" at 249.469,163.447 h1.52
  text "Int3" at 259.88,163.447 h1.52
  text "CF-005" at 293.653,163.447 h1.52
  text "2.76mil" at 308.889,163.447 h1.52
  text "Dielectric 6" at 259.88,160.399 h1.52
  text "Core-022" at 293.653,160.399 h1.52
  text "7.00mil" at 308.889,160.399 h1.52
  text "4.3" at 325.395,160.399 h1.52
  text "5" at 249.469,157.351 h1.52
  text "Int4" at 259.88,157.351 h1.52
  text "CF-005" at 293.653,157.351 h1.52
  text "2.76mil" at 308.889,157.351 h1.52
  text "Dielectric 7" at 259.88,154.303 h1.52
  text "PP-003" at 293.653,154.303 h1.52
  text "2.30mil" at 308.889,154.303 h1.52
  text "3.9" at 325.395,154.303 h1.52
  text "Dielectric 8" at 259.88,151.255 h1.52
  text "Core-036" at 293.653,151.255 h1.52
  text "20.00mil" at 308.889,151.255 h1.52
  text "4.6" at 325.395,151.255 h1.52
  text "6" at 249.469,148.207 h1.52
  text "Bottom Layer" at 259.88,148.207 h1.52
  text "CF-005" at 293.653,148.207 h1.52
  text "2.76mil" at 308.889,148.207 h1.52
  text "Bottom Surface Finish" at 259.88,145.159 h1.52
  text "PbSn" at 293.653,145.159 h1.52
  text "0.79mil" at 308.889,145.159 h1.52
  text "Bottom Solder" at 259.88,142.111 h1.52
  text "SM-001" at 293.653,142.111 h1.52
  text "1.00mil" at 308.889,142.111 h1.52
  text "4" at 325.395,142.111 h1.52
  text "Bottom Overlay" at 259.88,139.063 h1.52
  text ".Layer_Name" at 14.656,-21.806 h1.52
M13 Component Bodies Top:
  text ".Layer_Name" at 14.656,-21.806 h1.52
M14 Component Bodies Bottom:
  text ".Layer_Name" at 14.656,-21.806 h1.52
M15 Courtyards Top:
  text ".Layer_Name" at 14.656,-21.806 h1.52
M16 Courtyards Bottom:
  text ".Layer_Name" at 14.656,-21.806 h1.52
Drill Drawing:
  circle w0.254: c35.334,11.202 r0.702
  lines w0.254: 34.633,7.342 36.036,7.342 36.036,8.746 34.633,8.746 34.633,7.342
  lines w0.305: 33.36,6.395 115.44,6.395 ; 33.36,12.71 115.44,12.71 ; 41.942,3.237 41.942,15.868 ; 50.375,3.237 50.375,15.868 ; 66.544,3.237 66.544,15.868 ; 73.126,3.237 73.126,15.868 ; 82.655,3.237 82.655,15.868 ; 101.053,3.237 101.053,15.868 ; 33.36,3.237 115.44,3.237 115.44,15.868 33.36,15.868 33.36,3.237
  text "Symbol" at 35.255,13.658 h1.83
  text "Quantity" at 42.889,13.658 h1.83
  text "Finished Hole Size" at 51.322,13.658 h1.83
  text "Plated" at 67.491,13.658 h1.83
  text "Hole Type" at 74.073,13.658 h1.83
  text "Drill Layer Pair" at 83.602,13.658 h1.83
  text "Hole Tolerance" at 102,13.658 h1.83
  text "30" at 42.889,10.5 h1.52
  text "8.00mil (0.203mm)" at 51.322,10.5 h1.52
  text "PTH" at 67.491,10.5 h1.52
  text "Round" at 74.073,10.5 h1.52
  text "(Mixed)" at 83.602,10.5 h1.52
  text "18" at 42.889,7.342 h1.52
  text "27.56mil (0.700mm)" at 51.322,7.342 h1.52
  text "PTH" at 67.491,7.342 h1.52
  text "Round" at 74.073,7.342 h1.52
  text "Top Layer - Bottom Layer" at 83.602,7.342 h1.52
  text "48 Total" at 42.889,4.185 h1.52
  text ".Layer_Name" at 14.656,-21.806 h1.52
M17 Embedded Cavity:
  text ".Layer_Name" at 14.656,-21.806 h1.52
M18 Embedded Assembly:
  text ".Layer_Name" at 14.656,-21.806 h1.52
M19 Embedded Keepout:
  text ".Layer_Name" at 14.656,-21.806 h1.52

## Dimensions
0,-10.16 to 25.4,-10.16 on M2 Board Dimensions
12,18.65 to 12,1.35 on M2 Board Dimensions
0,0 to 30.3,2.144 on M2 Board Dimensions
